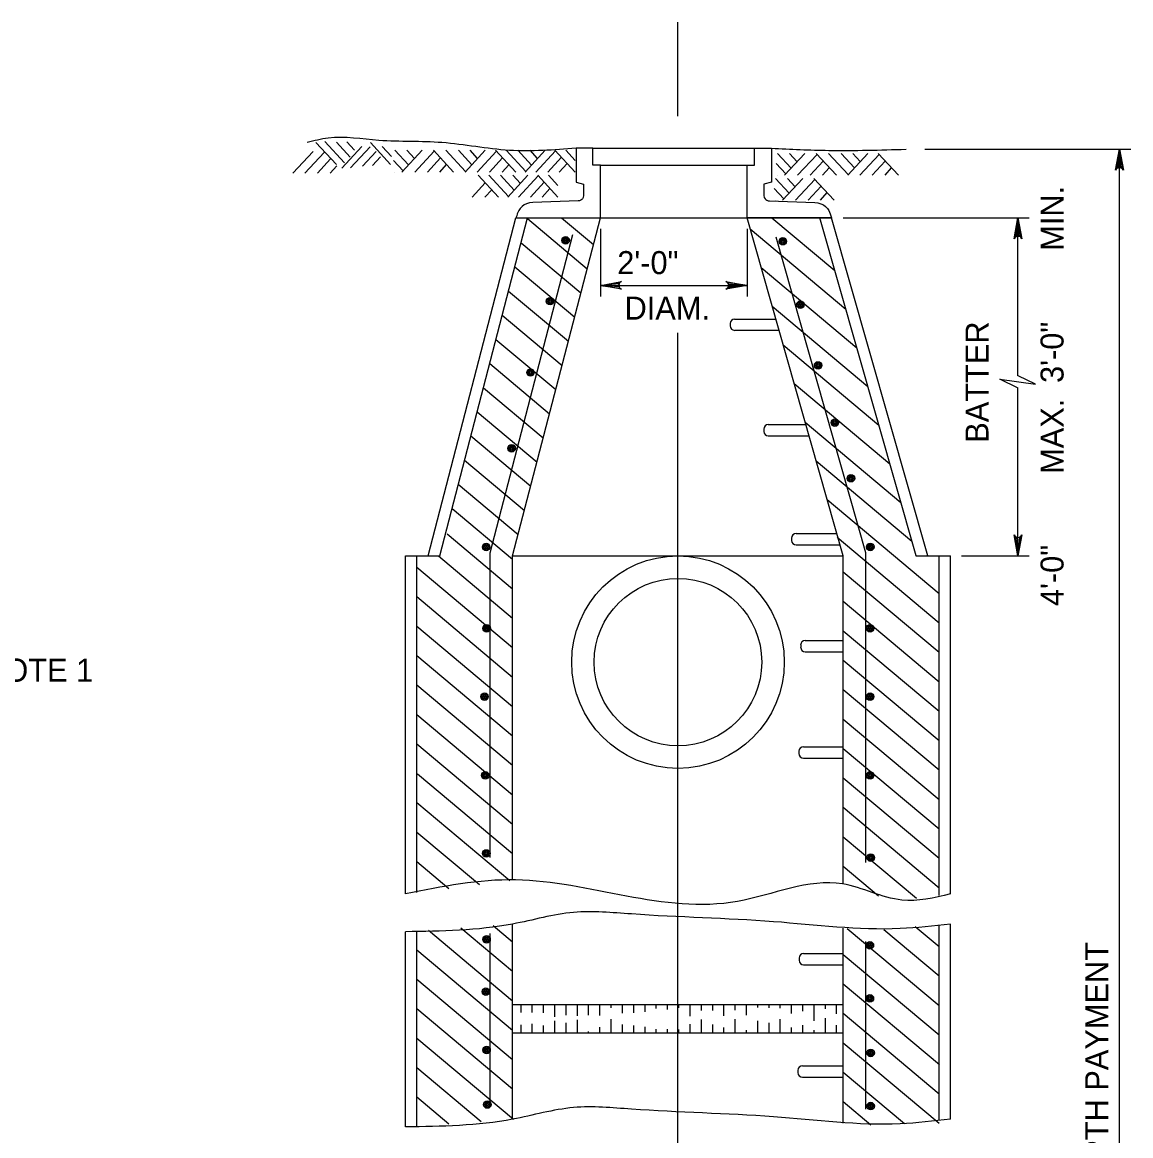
# Model space of a CAD drawing. Extents: x 0.2 to 7.1, y 1.2 to 11.2.
# Drawn here: x 3.289 to 6.181, y 5.546 to 8.452 of the extents above; entities that cross this region are included whole.
import ezdxf

# ---------------------------------------------------------------- set-up
doc = ezdxf.new("R2010")
doc.units = 0
for name, color, linetype in [('DETL-DIMS', 7, 'Continuous'), ('DETL-LINE', 7, 'Continuous'), ('DETL-NOTE', 7, 'Continuous'), ('DETL-PATT', 7, 'Continuous')]:
    doc.layers.add(name, color=color, linetype=linetype)

msp = doc.modelspace()

# ---------------------------------------------------------------- linework, layer by layer
at = {"layer": 'DETL-DIMS'}
for p, q in [((4.9995, 8.2067), (4.9995, 8.4516)), ((5.6434, 8.1202), (6.1809, 8.1202)), ((6.1514, 4.6226), (6.1514, 8.1202)), ((5.4308, 7.9415), (5.9161, 7.9415)), ((5.8867, 7.5293), (5.8867, 7.9415)), ((4.7973, 7.9121), (4.7973, 7.7356)), ((5.1797, 7.9121), (5.1797, 7.7356)), ((4.7973, 7.765), (5.1797, 7.765)), ((4.9995, 3.3192), (4.9995, 7.6411)), ((5.8867, 7.0591), (5.8867, 7.497)), ((5.7397, 7.0591), (5.9161, 7.0591))]:
    msp.add_line(p, q, dxfattribs=at)
for points in [[(6.1514, 8.1202), (6.1617, 8.0654), (6.1588, 8.0696), (6.1551, 8.0718), (6.1514, 8.0724), (6.1478, 8.0718), (6.1441, 8.0696), (6.1412, 8.0654), (6.1514, 8.1202), (6.1441, 8.0696), (6.1478, 8.0718), (6.1514, 8.1202), (6.1514, 8.0724), (6.1551, 8.0718), (6.1514, 8.1202), (6.1588, 8.0696)], [(5.8867, 7.9415), (5.897, 7.8866), (5.8941, 7.8909), (5.8904, 7.8931), (5.8867, 7.8937), (5.8831, 7.8931), (5.8794, 7.8909), (5.8765, 7.8866), (5.8867, 7.9415), (5.8794, 7.8909), (5.8831, 7.8931), (5.8867, 7.9415), (5.8867, 7.8937), (5.8904, 7.8931), (5.8867, 7.9415), (5.8941, 7.8909)], [(4.7973, 7.765), (4.8521, 7.7753), (4.8479, 7.7724), (4.8457, 7.7687), (4.8451, 7.765), (4.8457, 7.7613), (4.8479, 7.7577), (4.8521, 7.7547), (4.7973, 7.765), (4.8479, 7.7577), (4.8457, 7.7613), (4.7973, 7.765), (4.8451, 7.765), (4.8457, 7.7687), (4.7973, 7.765), (4.8479, 7.7724)], [(5.1797, 7.765), (5.1248, 7.7547), (5.1291, 7.7577), (5.1312, 7.7613), (5.1319, 7.765), (5.1312, 7.7687), (5.1291, 7.7724), (5.1248, 7.7753), (5.1797, 7.765), (5.1291, 7.7724), (5.1312, 7.7687), (5.1797, 7.765), (5.1319, 7.765), (5.1312, 7.7613), (5.1797, 7.765), (5.1291, 7.7577)], [(5.8869, 7.4969), (5.8392, 7.5202), (5.9325, 7.5075), (5.8869, 7.5292)], [(5.8867, 7.0591), (5.8765, 7.114), (5.8794, 7.1097), (5.8831, 7.1075), (5.8867, 7.1069), (5.8904, 7.1075), (5.8941, 7.1097), (5.897, 7.114), (5.8867, 7.0591), (5.8941, 7.1097), (5.8904, 7.1075), (5.8867, 7.0591), (5.8867, 7.1069), (5.8831, 7.1075), (5.8867, 7.0591), (5.8794, 7.1097)]]:
    msp.add_lwpolyline(points, dxfattribs=at)
at = {"layer": 'DETL-LINE'}
for p, q in [((4.7777, 8.1228), (5.1993, 8.1228)), ((4.7973, 8.0787), (5.1797, 8.0787)), ((4.3475, 7.0591), (4.5767, 7.9415)), ((4.3779, 7.0591), (4.6071, 7.9415)), ((4.5681, 7.0591), (4.7973, 7.9415)), ((4.5767, 7.9415), (5.4003, 7.9415)), ((5.4309, 7.0591), (5.1797, 7.9415)), ((5.6209, 7.0591), (5.3697, 7.9415)), ((5.6514, 7.0591), (5.4003, 7.9415)), ((4.5093, 7.0666), (4.7251, 7.8973)), ((5.4897, 7.0673), (5.2553, 7.8906)), ((5.1473, 7.6771), (5.2549, 7.6771)), ((5.1355, 7.6653), (5.1355, 7.6594)), ((5.1473, 7.6477), (5.2633, 7.6477)), ((5.2233, 7.3899), (5.2233, 7.384)), ((5.2351, 7.4016), (5.3334, 7.4016)), ((5.2351, 7.3722), (5.3417, 7.3722)), ((5.2961, 7.1053), (5.2961, 7.0995)), ((5.3078, 7.1171), (5.4143, 7.1171)), ((4.5093, 6.2717), (4.5093, 7.0666)), ((5.3078, 7.0877), (5.4227, 7.0877)), ((5.4897, 6.2591), (5.4897, 7.0673)), ((4.2887, 6.1768), (4.2887, 7.0591)), ((4.2887, 7.0591), (4.3779, 7.0591)), ((4.3181, 6.1805), (4.3181, 7.0591)), ((4.5681, 6.2126), (4.5681, 7.0591)), ((4.5681, 7.0591), (5.4309, 7.0591)), ((5.4309, 6.203), (5.4309, 7.0591)), ((5.6204, 7.0591), (5.7103, 7.0591)), ((5.6809, 6.1731), (5.6809, 7.0591)), ((5.7103, 6.1768), (5.7103, 7.0591)), ((5.3314, 6.8384), (5.4309, 6.8384)), ((5.3197, 6.8266), (5.3197, 6.8207)), ((5.3314, 6.809), (5.4309, 6.809)), ((5.3153, 6.549), (5.3153, 6.5432)), ((5.327, 6.5608), (5.4309, 6.5608)), ((5.327, 6.5314), (5.4309, 6.5314)), ((4.2887, 5.5689), (4.2887, 6.0782)), ((4.3181, 5.571), (4.3181, 6.0804)), ((4.5093, 5.9053), (4.5093, 6.0739)), ((4.5681, 5.589), (4.5681, 6.0983)), ((5.4309, 5.5785), (5.4309, 6.0878)), ((5.6809, 5.5863), (5.6809, 6.0956)), ((5.7103, 5.589), (5.7103, 6.0983)), ((5.4897, 5.6155), (5.4897, 6.0525)), ((5.3274, 6.0214), (5.4309, 6.0214)), ((5.3157, 6.0096), (5.3157, 6.0037)), ((5.3274, 5.992), (5.4309, 5.992)), ((4.5093, 5.6233), (4.5093, 5.9461)), ((5.4309, 5.8874), (4.5681, 5.8874)), ((5.4309, 5.8139), (4.5681, 5.8139)), ((5.3243, 5.7283), (5.4309, 5.7283)), ((5.3126, 5.7165), (5.3126, 5.7106)), ((5.3243, 5.6989), (5.4309, 5.6989))]:
    msp.add_line(p, q, dxfattribs=at)
for points in [[(4.7336, 8.1228), (4.7336, 8.0346), (4.7532, 8.0289), (4.7532, 7.9999), (4.7525, 7.9942), (4.7504, 7.991), (4.7483, 7.9893), (4.7459, 7.9872), (4.7425, 7.9855), (4.7389, 7.9852), (4.6206, 7.9816), (4.6124, 7.9806), (4.6044, 7.9778), (4.5982, 7.9751), (4.5927, 7.9709), (4.5875, 7.9657), (4.584, 7.9602), (4.5802, 7.9518), (4.5788, 7.9463), (4.5767, 7.9415), (4.7973, 7.9415), (4.7973, 8.0787), (4.7777, 8.0787), (4.7777, 8.1228)], [(5.2434, 8.1228), (5.2434, 8.0346), (5.2238, 8.0289), (5.2238, 7.9999), (5.2245, 7.9942), (5.2266, 7.991), (5.2286, 7.9893), (5.2311, 7.9872), (5.2345, 7.9855), (5.2381, 7.9852), (5.3564, 7.9816), (5.3646, 7.9806), (5.3725, 7.9778), (5.3788, 7.9751), (5.3843, 7.9709), (5.3895, 7.9657), (5.393, 7.9602), (5.3968, 7.9518), (5.3982, 7.9463), (5.4003, 7.9415), (5.1797, 7.9415), (5.1797, 8.0787), (5.1993, 8.0787), (5.1993, 8.1228)]]:
    msp.add_lwpolyline(points, close=True, dxfattribs=at)
for centre, radius in [((4.7064, 7.8825), 0.0098), ((4.7064, 7.8825), 0.00735), ((4.7064, 7.8825), 0.0049), ((4.7064, 7.8825), 0.00245), ((5.2732, 7.8802), 0.0098), ((5.2732, 7.8802), 0.00735), ((5.2732, 7.8802), 0.0049), ((5.2732, 7.8802), 0.00245), ((4.6658, 7.7238), 0.0098), ((4.6658, 7.7238), 0.00735), ((4.6658, 7.7238), 0.0049), ((4.6658, 7.7238), 0.00245), ((5.319, 7.7146), 0.0098), ((5.319, 7.7146), 0.00735), ((5.319, 7.7146), 0.0049), ((5.319, 7.7146), 0.00245), ((5.3652, 7.556), 0.0098), ((5.3652, 7.556), 0.00735), ((5.3652, 7.556), 0.0049), ((5.3652, 7.556), 0.00245), ((4.6147, 7.5376), 0.0098), ((4.6147, 7.5376), 0.00735), ((4.6147, 7.5376), 0.0049), ((4.6147, 7.5376), 0.00245), ((5.4089, 7.4065), 0.0098), ((5.4089, 7.4065), 0.00735), ((5.4089, 7.4065), 0.0049), ((5.4089, 7.4065), 0.00245), ((4.5655, 7.3399), 0.0098), ((4.5655, 7.3399), 0.00735), ((4.5655, 7.3399), 0.0049), ((4.5655, 7.3399), 0.00245), ((5.4508, 7.2617), 0.0098), ((5.4508, 7.2617), 0.00735), ((5.4508, 7.2617), 0.0049), ((5.4508, 7.2617), 0.00245), ((4.499, 7.0823), 0.0098), ((5.5013, 7.0823), 0.0098), ((4.499, 7.0823), 0.00735), ((4.499, 7.0823), 0.0049), ((4.499, 7.0823), 0.00245), ((5.5013, 7.0823), 0.00735), ((5.5013, 7.0823), 0.0049), ((5.5013, 7.0823), 0.00245), ((4.9995, 6.7818), 0.2773), ((4.9995, 6.7818), 0.2185), ((4.5002, 6.8701), 0.0098), ((4.5002, 6.8701), 0.00735), ((4.5002, 6.8701), 0.0049), ((4.5002, 6.8701), 0.00245), ((5.5008, 6.8701), 0.0098), ((5.5008, 6.8701), 0.00735), ((5.5008, 6.8701), 0.0049), ((5.5008, 6.8701), 0.00245), ((4.4948, 6.6916), 0.0098), ((4.4948, 6.6916), 0.00735), ((4.4948, 6.6916), 0.0049), ((4.4948, 6.6916), 0.00245), ((5.5008, 6.6916), 0.0098), ((5.5008, 6.6916), 0.00735), ((5.5008, 6.6916), 0.0049), ((5.5008, 6.6916), 0.00245), ((4.4966, 6.4862), 0.0098), ((4.4966, 6.4862), 0.00735), ((4.4966, 6.4862), 0.0049), ((4.4966, 6.4862), 0.00245), ((5.5008, 6.4862), 0.0098), ((5.5008, 6.4862), 0.00735), ((5.5008, 6.4862), 0.0049), ((5.5008, 6.4862), 0.00245), ((4.4993, 6.2825), 0.0098), ((4.4993, 6.2825), 0.00735), ((4.4993, 6.2825), 0.0049), ((4.4993, 6.2825), 0.00245), ((5.5026, 6.2717), 0.0098), ((5.5026, 6.2717), 0.00735), ((5.5026, 6.2717), 0.0049), ((5.5026, 6.2717), 0.00245), ((4.5001, 6.0583), 0.0098), ((4.5001, 6.0583), 0.00735), ((4.5001, 6.0583), 0.0049), ((4.5001, 6.0583), 0.00245), ((5.5003, 6.0427), 0.0098), ((5.5003, 6.0427), 0.00735), ((5.5003, 6.0427), 0.0049), ((5.5003, 6.0427), 0.00245), ((4.4982, 5.9218), 0.0098), ((4.4982, 5.9218), 0.00735), ((4.4982, 5.9218), 0.0049), ((4.4982, 5.9218), 0.00245), ((5.5003, 5.9042), 0.0098), ((5.5003, 5.9042), 0.00735), ((5.5003, 5.9042), 0.0049), ((5.5003, 5.9042), 0.00245), ((4.5001, 5.7696), 0.0098), ((4.5001, 5.7696), 0.00735), ((4.5001, 5.7696), 0.0049), ((4.5001, 5.7696), 0.00245), ((5.5023, 5.7618), 0.0098), ((5.5023, 5.7618), 0.00735), ((5.5023, 5.7618), 0.0049), ((5.5023, 5.7618), 0.00245), ((4.5021, 5.6272), 0.0098), ((4.5021, 5.6272), 0.00735), ((4.5021, 5.6272), 0.0049), ((4.5021, 5.6272), 0.00245), ((5.5023, 5.6233), 0.0098), ((5.5023, 5.6233), 0.00735), ((5.5023, 5.6233), 0.0049), ((5.5023, 5.6233), 0.00245)]:
    msp.add_circle(centre, radius, dxfattribs=at)
for centre, start, end in [((5.1473, 7.6653), 90, 180), ((5.1473, 7.6594), 180, 270), ((5.2351, 7.3899), 90, 180), ((5.2351, 7.384), 180, 270), ((5.3078, 7.1053), 90, 180), ((5.3078, 7.0995), 180, 270), ((5.3314, 6.8266), 90, 180), ((5.3314, 6.8207), 180, 270), ((5.327, 6.549), 90, 180), ((5.327, 6.5432), 180, 270), ((5.3274, 6.0096), 90, 180), ((5.3274, 6.0037), 180, 270), ((5.3243, 5.7165), 90, 180), ((5.3243, 5.7106), 180, 270)]:
    msp.add_arc(centre, 0.0118, start, end, dxfattribs=at)
for points in [[(4.7336, 8.1228), (4.5596, 8.1173), (4.3838, 8.1375), (4.2194, 8.1433), (4.0868, 8.1491), (4.032, 8.1375)], [(5.2434, 8.1228), (5.3929, 8.1173), (5.5947, 8.1202)], [(5.7103, 6.1768), (5.5836, 6.1608), (5.4291, 6.203), (5.1551, 6.1573), (4.5757, 6.2135), (4.2887, 6.1768)], [(5.7103, 6.0983), (5.5792, 6.0863), (5.2489, 6.1044), (4.8782, 6.1245), (4.7272, 6.1286), (4.5681, 6.0983), (4.2887, 6.0782)], [(5.7103, 5.589), (5.5792, 5.5769), (5.2489, 5.5951), (4.8782, 5.6152), (4.7272, 5.6193), (4.5681, 5.589), (4.2887, 5.5689)]]:
    msp.add_spline(points, degree=3, dxfattribs=at)
at = {"layer": 'DETL-PATT'}
for p, q in [((4.1083, 8.0805), (4.0549, 8.1374)), ((4.1296, 8.0849), (4.0783, 8.1401)), ((4.1439, 8.0996), (4.1082, 8.1383)), ((4.1553, 8.1176), (4.1355, 8.1392)), ((4.2495, 8.0805), (4.1969, 8.1374)), ((3.9948, 8.0578), (4.0474, 8.1147)), ((4.0262, 8.0578), (4.0764, 8.1119)), ((4.1224, 8.0705), (4.175, 8.1276)), ((4.1452, 8.0714), (4.1961, 8.1265)), ((4.1763, 8.0759), (4.2117, 8.1146)), ((4.2523, 8.1009), (4.2279, 8.1274)), ((4.2965, 8.0793), (4.2608, 8.1175)), ((4.2792, 8.0606), (4.3319, 8.1175)), ((4.3117, 8.0957), (4.2919, 8.1175)), ((4.3131, 8.0606), (4.3637, 8.1148)), ((4.4142, 8.0606), (4.3612, 8.1175)), ((4.4453, 8.0621), (4.3941, 8.1175)), ((4.4616, 8.0798), (4.4269, 8.1175)), ((4.4439, 8.0606), (4.4966, 8.1175)), ((4.4764, 8.0964), (4.4573, 8.1175)), ((4.4754, 8.0606), (4.5255, 8.1146)), ((4.5764, 8.0606), (4.5231, 8.1175)), ((4.6022, 8.0623), (4.551, 8.1175)), ((4.6174, 8.0788), (4.5817, 8.1175)), ((4.6005, 8.0606), (4.6531, 8.1176)), ((4.6333, 8.0959), (4.6136, 8.1175)), ((4.6287, 8.0606), (4.6796, 8.1157)), ((4.7312, 8.0606), (4.6786, 8.1175)), ((4.7312, 8.0909), (4.7069, 8.1175)), ((5.2951, 8.0711), (5.2594, 8.1093)), ((5.2778, 8.0524), (5.3305, 8.1093)), ((5.3103, 8.0876), (5.2905, 8.1093)), ((5.4128, 8.0524), (5.3598, 8.1093)), ((5.4439, 8.054), (5.3927, 8.1093)), ((5.4602, 8.0717), (5.4255, 8.1093)), ((5.4425, 8.0524), (5.4952, 8.1093)), ((5.475, 8.0883), (5.4559, 8.1093)), ((5.575, 8.0524), (5.5217, 8.1093)), ((4.0587, 8.0578), (4.0927, 8.0948)), ((4.2028, 8.0777), (4.2233, 8.1002)), ((4.2824, 8.0641), (4.2573, 8.0909)), ((4.3457, 8.0606), (4.3799, 8.0975)), ((4.3778, 8.0606), (4.3958, 8.0802)), ((4.5079, 8.0606), (4.5418, 8.0975)), ((4.5411, 8.0606), (4.5584, 8.0796)), ((4.6599, 8.0606), (4.6952, 8.0993)), ((4.6899, 8.0606), (4.7104, 8.083)), ((5.281, 8.0559), (5.2559, 8.0828)), ((5.3117, 8.0524), (5.3623, 8.1067)), ((5.3443, 8.0524), (5.3785, 8.0893)), ((5.474, 8.0524), (5.5242, 8.1065)), ((5.5065, 8.0524), (5.5404, 8.0893)), ((4.092, 8.0578), (4.1093, 8.0769)), ((4.2607, 8.0606), (4.2607, 8.0606)), ((4.5314, 7.9955), (4.478, 8.0524)), ((4.5572, 7.9972), (4.5059, 8.0524)), ((4.5724, 8.0137), (4.5367, 8.0524)), ((4.5554, 7.9955), (4.6081, 8.0525)), ((4.5883, 8.0308), (4.5685, 8.0524)), ((4.5837, 7.9955), (4.6346, 8.0506)), ((4.6862, 7.9955), (4.6335, 8.0524)), ((4.6862, 8.0258), (4.6618, 8.0524)), ((5.2593, 8.0524), (5.2593, 8.0524)), ((5.3764, 8.0524), (5.3944, 8.072)), ((5.5397, 8.0524), (5.557, 8.0715)), ((4.4628, 7.9955), (4.4968, 8.0324)), ((4.6148, 7.9955), (4.6501, 8.0342)), ((5.2897, 8.006), (5.254, 8.0442)), ((5.2724, 7.9873), (5.3251, 8.0442)), ((5.3049, 8.0225), (5.2851, 8.0442)), ((5.3063, 7.9873), (5.3569, 8.0415)), ((5.3388, 7.9873), (5.3731, 8.0242)), ((5.4074, 7.9873), (5.3544, 8.0442)), ((4.496, 7.9955), (4.5134, 8.0145)), ((4.6448, 7.9955), (4.6653, 8.0179)), ((5.2756, 7.9908), (5.2505, 8.0177)), ((5.371, 7.9873), (5.389, 8.0069)), ((5.2538, 7.9873), (5.2538, 7.9873)), ((4.6065, 7.9393), (4.7627, 7.8082)), ((4.6954, 7.9415), (4.7791, 7.8713)), ((5.2445, 7.9415), (5.409, 7.8035)), ((5.188, 7.9121), (5.4377, 7.7026)), ((4.5902, 7.8762), (4.7463, 7.7452)), ((4.5738, 7.8132), (4.73, 7.6822)), ((5.2168, 7.8112), (5.4664, 7.6017)), ((4.5574, 7.7501), (4.7136, 7.6191)), ((5.2455, 7.7103), (5.4951, 7.5008)), ((4.541, 7.6871), (4.6972, 7.5561)), ((4.5247, 7.6241), (4.6808, 7.493)), ((5.2742, 7.6094), (5.5238, 7.4)), ((4.5083, 7.561), (4.6644, 7.43)), ((4.4919, 7.498), (4.6481, 7.3669)), ((5.3029, 7.5085), (5.5526, 7.2991)), ((4.4755, 7.4349), (4.6317, 7.3039)), ((5.3316, 7.4076), (5.5813, 7.1982)), ((4.4591, 7.3719), (4.6153, 7.2408)), ((4.4428, 7.3088), (4.5989, 7.1778)), ((5.3604, 7.3068), (5.61, 7.0973)), ((4.4264, 7.2458), (4.5826, 7.1147)), ((4.41, 7.1827), (4.5681, 7.0501)), ((5.3891, 7.2059), (5.6809, 6.961)), ((4.3976, 7.1164), (4.5681, 6.9733)), ((5.4147, 7.1076), (5.6809, 6.8843)), ((4.3743, 7.0591), (4.5681, 6.8965)), ((4.3181, 7.0295), (4.5681, 6.8197)), ((5.4309, 7.0172), (5.6809, 6.8075)), ((4.3181, 6.9527), (4.5681, 6.7429)), ((5.4309, 6.9405), (5.6809, 6.7307)), ((4.3181, 6.8759), (4.5681, 6.6661)), ((5.4309, 6.8637), (5.6809, 6.6539)), ((4.3181, 6.7991), (4.5681, 6.5893)), ((5.4309, 6.7869), (5.6809, 6.5771)), ((4.3181, 6.7223), (4.5681, 6.5126)), ((5.4309, 6.7101), (5.6809, 6.5003)), ((4.3181, 6.6455), (4.5681, 6.4358)), ((5.4309, 6.6333), (5.6809, 6.4235)), ((4.3181, 6.5687), (4.5681, 6.359)), ((5.4309, 6.5565), (5.6809, 6.3467)), ((4.3199, 6.4905), (4.5681, 6.2822)), ((5.4309, 6.4797), (5.6809, 6.2699)), ((4.3181, 6.4152), (4.5607, 6.2116)), ((5.4309, 6.4029), (5.6809, 6.1932)), ((4.3181, 6.3384), (4.4813, 6.2014)), ((5.4309, 6.3261), (5.6221, 6.1657)), ((4.3181, 6.2616), (4.4019, 6.1913)), ((5.4309, 6.2494), (5.523, 6.172)), ((4.3485, 6.0825), (4.5681, 5.8982)), ((4.4328, 6.0886), (4.5681, 5.975)), ((4.517, 6.0947), (4.5681, 6.0518)), ((5.4413, 6.087), (5.6809, 5.886)), ((5.5366, 6.0839), (5.6809, 5.9628)), ((5.6187, 6.0918), (5.6809, 6.0396)), ((4.3181, 6.0312), (4.5681, 5.8215)), ((5.4309, 6.019), (5.6809, 5.8092)), ((4.3181, 5.9544), (4.5681, 5.7447)), ((5.4309, 5.9422), (5.6817, 5.7317)), ((4.3181, 5.8777), (4.5681, 5.6679)), ((4.5892, 5.8874), (4.5892, 5.8676)), ((4.6186, 5.8874), (4.6186, 5.8676)), ((4.648, 5.8874), (4.648, 5.8666)), ((4.6774, 5.8874), (4.6774, 5.8565)), ((4.7068, 5.8874), (4.7068, 5.8605)), ((4.7362, 5.8874), (4.7362, 5.8585)), ((4.7656, 5.8874), (4.7656, 5.8605)), ((4.7951, 5.8874), (4.7951, 5.8595)), ((4.8245, 5.8874), (4.8245, 5.8797)), ((4.8539, 5.8874), (4.8539, 5.8656)), ((4.8833, 5.8874), (4.8833, 5.8666)), ((4.9127, 5.8874), (4.9127, 5.8696)), ((4.9421, 5.8874), (4.9421, 5.8777)), ((4.9715, 5.8874), (4.9715, 5.8757)), ((5.0009, 5.8874), (5.0009, 5.8797)), ((5.0304, 5.8874), (5.0304, 5.8575)), ((5.0598, 5.8874), (5.0598, 5.8727)), ((5.0892, 5.8874), (5.0892, 5.8727)), ((5.1186, 5.8874), (5.1186, 5.8585)), ((5.148, 5.8874), (5.148, 5.8737)), ((5.1774, 5.8874), (5.1774, 5.8605)), ((5.2068, 5.8874), (5.2068, 5.8807)), ((5.2362, 5.8874), (5.2362, 5.8797)), ((5.2656, 5.8874), (5.2656, 5.8787)), ((5.2951, 5.8874), (5.2951, 5.8646)), ((5.3245, 5.8874), (5.3245, 5.8706)), ((5.3539, 5.8874), (5.3539, 5.8454)), ((5.3833, 5.8874), (5.3833, 5.8767)), ((5.4127, 5.8874), (5.4127, 5.8636)), ((4.6774, 5.8454), (4.6774, 5.8139)), ((4.7362, 5.8484), (4.7362, 5.8139)), ((4.8245, 5.8504), (4.8245, 5.8139)), ((5.0598, 5.8494), (5.0598, 5.8139)), ((5.148, 5.8504), (5.148, 5.8139)), ((5.2068, 5.8454), (5.2068, 5.8139)), ((5.2656, 5.8504), (5.2656, 5.8139)), ((5.3833, 5.8524), (5.3833, 5.8139)), ((5.4309, 5.8654), (5.6809, 5.6556)), ((4.5892, 5.8353), (4.5892, 5.8139)), ((4.6186, 5.8383), (4.6186, 5.8139)), ((4.648, 5.8332), (4.648, 5.8139)), ((4.7068, 5.8403), (4.7068, 5.8139)), ((4.7656, 5.8181), (4.7656, 5.8139)), ((4.7951, 5.8292), (4.7951, 5.8139)), ((4.8539, 5.8363), (4.8539, 5.8139)), ((4.8833, 5.8332), (4.8833, 5.8139)), ((4.9127, 5.8302), (4.9127, 5.8139)), ((4.9421, 5.8241), (4.9421, 5.8139)), ((4.9715, 5.8241), (4.9715, 5.8139)), ((5.0009, 5.8231), (5.0009, 5.8139)), ((5.0304, 5.8373), (5.0304, 5.8139)), ((5.0892, 5.8363), (5.0892, 5.8139)), ((5.1186, 5.8282), (5.1186, 5.8139)), ((5.1774, 5.8211), (5.1774, 5.8139)), ((5.2362, 5.8403), (5.2362, 5.8139)), ((5.2951, 5.8282), (5.2951, 5.8139)), ((5.3245, 5.8343), (5.3245, 5.8139)), ((5.3539, 5.8211), (5.3539, 5.8139)), ((5.4127, 5.8343), (5.4127, 5.8139)), ((4.3181, 5.8009), (4.5704, 5.5892)), ((5.4309, 5.7886), (5.6809, 5.5788)), ((4.3181, 5.7241), (4.4861, 5.5831)), ((5.4309, 5.7118), (5.5904, 5.578)), ((4.3181, 5.6473), (4.4018, 5.5771)), ((5.4309, 5.635), (5.503, 5.5745))]:
    msp.add_line(p, q, dxfattribs=at)

# ---------------------------------------------------------------- texts
at = {"layer": 'DETL-NOTE'}
for s, p in [('MIN.', (6.0056, 7.8552)), ('BATTER', (5.8098, 7.3543)), ('3\'-0"', (6.0056, 7.5103)), ('MAX.', (6.0056, 7.273)), ('4\'-0"', (6.0056, 6.9281)), ('11\'-0" MIN. DEPTH PAYMENT', (6.122, 4.9509))]:
    msp.add_text(s, height=0.06, rotation=90, dxfattribs=at).set_placement(p)
for s, p in [('2\'-0"', (4.8411, 7.7944)), ('DIAM.', (4.8602, 7.6756)), ('SEE NOTE 1', (3.0011, 6.7308))]:
    msp.add_text(s, height=0.06, dxfattribs=at).set_placement(p)

doc.saveas('drawing.dxf')
